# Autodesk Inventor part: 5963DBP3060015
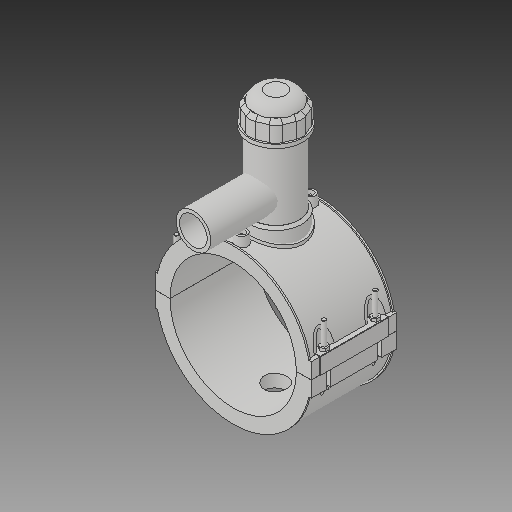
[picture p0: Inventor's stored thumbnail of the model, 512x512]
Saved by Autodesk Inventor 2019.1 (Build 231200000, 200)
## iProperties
Created: 2017-07
Part Number: 5963DBP3060015
Material: Generic
Description: PLASSON TAPPING SADDLE 6''DIPS x 1 1/2''IPS
Document SubType Name: Modeling
Designer: KIM
Density: 1 g/cm^3
Appearance: Default
Author: KIM
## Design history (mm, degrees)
derived "5963DBP_5963BUP.ipt"
feature "Solid1::5963DBP_5963BUP.ipt"
feature "Solid2::5963DBP_5963BUP.ipt"
feature "Solid3::5963DBP_5963BUP.ipt"
tag "TaggingFeature1"
body "Solid1"
body "Solid2"
body "Solid3"
other parameters: "d0" = 174.5, "d2" = 215.9, "d3" = 43.625, "d4" = 118.11, "d5" = 0, "d6" = 0.1, "d8" = 0, "d19" = 6, "d20" = 6, "d21" = 70.866, "d23" = 0, "d24" = 35.433, "d26" = 0, "d27" = 3, "d28" = 3, "d29" = 3, "d30" = 58.16667, "d31" = 6, "d32" = 0, "d33" = 0, "d34" = 0.6, "d40" = 108.888, "d41" = 75.035, "d43" = 0, "d45" = 0, "d47" = 175.566, "d70" = 15, "d72" = 0, "d73" = 6, "d75" = 5, "d76" = 0, "d77" = 8.725, "d78" = 117.25, "d79" = 15, "d80" = 47.244, "d82" = 5 deg, "d84" = 4, "d85" = 14, "d86" = 0, "d87" = 3, "d88" = 0, "d89" = 1, "d90" = 1, "d91" = 94.488, "d92" = 0, "d93" = 0.5, "d94" = 91.84211, "d96" = 213.588, "d97" = 2.3622, "d98" = 0, "d120" = 140 deg, "d121" = 24.228, "d122" = 20 deg, "d123" = 418.8, "d124" = 125.64, "d126" = 0, "d143" = 179.735, "d145" = 26.84615, "d149" = 2.6175, "d150" = 29.53077, "d153" = 118.11, "d154" = 0, "d156" = 104.7, "d157" = 160 deg, "d159" = 6.98, "d161" = 2.6175, "d162" = 70.866, "d163" = 0, "d164" = 87.25, "d167" = 17.45, "d168" = 102.14634, "d170" = 3.4335, "d172" = 0, "d173" = 1, "d175" = 87.25, "d176" = 20 deg, "d177" = 12.215, "d178" = 34.9, "d180" = 0, "d183" = 13.96, "d184" = 9.772, "d185" = 38.38575, "d186" = 38.38575, "d187" = 104.7, "d188" = 10.47, "d189" = 12.215, "d190" = 0, "d191" = 157.05, "d193" = 7.3248, "d194" = 4.13385, "d195" = 90 deg, "d197" = 0, "d199" = 0, "d200" = 17.45, "d202" = 0, "d203" = 177.038, "d204" = 71.28325, "d205" = 52.5245, "d206" = 63.77975, "d207" = 132.7785, "d208" = 138.08964, "d209" = 164.64534, "d210" = 64.5301, "d211" = 75.035, "d212" = 60.028, "d213" = 36.8766, "d216" = 0, "d217" = 17.45, "d218" = 17.45, "d219" = 3.49, "d222" = 174.5, "d224" = 0, "d225" = 65.024, "d226" = 48.1, "d227" = 38.48, "d228" = 114.046, "d230" = 5.235, "d_" = 174.5, "B_" = 215.9, "L_" = 118.11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
